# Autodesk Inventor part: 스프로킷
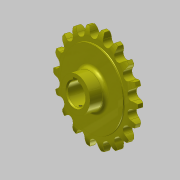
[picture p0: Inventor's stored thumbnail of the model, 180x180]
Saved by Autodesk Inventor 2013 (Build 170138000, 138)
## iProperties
Created: 2016-03
Part Number: 스프로킷
Material: 강철, 탄소
Document SubType Name: Modeling
Designer: mduedu
Density: 7.87 g/cm^3
Mass: 300.005 g
Surface Area: 127.848 cm^2
Volume: 38.12 cm^3
Author: mduedu
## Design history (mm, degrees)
sketch "스케치1"
  geometry: L1 (0, 5)-(29.5, 5); L2 (29.5, 5)-(29.5, 4.1); L3 (30, 3.6)-(33.625, 3.6); L4 (40, 2)-(40, 0); L5 (40, 0)-(0, 0); L6 (0, 0)-(0, 5); L7 (0, -5)-(29.5, -5); L8 (29.5, -5)-(29.5, -4.1); L9 (30, -3.6)-(33.625, -3.6); L10 (40, -2)-(40, 0); L11 (0, 0)-(0, -5); A1 r 13.5 centre (33.625, -9.9) between (40, 2) and (33.625, 3.6); A2 r 13.5 centre (33.625, 9.9) between (33.625, -3.6) and (40, -2); A3 r 0.5 centre (30, 4.1) between (29.5, 4.1) and (30, 3.6); A4 r 0.5 centre (30, -4.1) between (30, -3.6) and (29.5, -4.1); 2 further points
  constraints: 22 end point, 8 point on circle, 6 symmetric about line, 5 tangent, 4 centre point, 4 parallel, 4 point on line, 1 equal radius, 1 horizontal, 1 perpendicular, 1 other
  dimensions: "d0" = 80 diameter of L4 L6; "d2" = 59 diameter of L2 L6; "d3" = 1.6 vertical distance of L4.start L3.end; "d4" = 3.6 distance from line of L4.end L3; "d5" = 5 distance between parallel lines of L5 L1; "d6" = 13.5 radius of A1; "d15" = 0.5 radius of A3
revolve "회전1" sketch "스케치1" stored, may be unused: angle "d7" = 90 deg
sketch "스케치2" dims "d8" = 65.2, "d11" = 80
  geometry: L1 (0, 0)-(0, 32.6); A1 r 36.57 centre (0, 0) between (-16.231, 32.771) and (0, 36.57); A2 r 3.97 centre (0, 36.57) between (-3.866, 35.665) and (0, 32.6); A3 r 12.7 centre (-16.231, 32.771) between (-3.866, 35.665) and (-5.534, 39.615); A4 r 12.7 centre (16.231, 32.771) between (5.534, 39.615) and (3.866, 35.665); A5 r 3.97 centre (0, 36.57) between (0, 32.6) and (3.866, 35.665); A6 r 40 centre (0, 0) between (5.534, 39.615) and (-5.534, 39.615); 2 further points
  constraints: 12 point on circle, 6 centre point, 4 coincident, 3 symmetric about line, 2 end point, 1 point on line, 1 tangent, 1 vertical, 1 vertical alignment, 7 other
  dimensions: "d10" = 73.14 diameter of A1; "d12" = 12.7 radius of A3
extrude "돌출1" cut sketch "스케치2" stored distance "d13" = 10; taper "d14" = 0 deg
sketch "스케치3"
  geometry: C1 r 13.5 at (0, 0); 1 further point
  constraints: 1 centre point, 1 coincident
  dimensions: "d19" = 27 diameter of C1
extrude "돌출2" join sketch "스케치3" distance "d20" = 13; taper "d21" = 0 deg
fillet "모깎기1" dims "d22" = 3
sketch "스케치4"
  geometry: L1 (-2.5, 0)-(2.5, 0); L2 (2.5, 0)-(2.5, 10.8); L3 (2.5, 10.8)-(-2.5, 10.8); L4 (-2.5, 10.8)-(-2.5, 0); C1 r 8.5 at (0, 0); 2 further points
  constraints: 8 end point, 2 coincident, 2 parallel, 1 centre point, 1 horizontal, 1 midpoint, 1 perpendicular
  dimensions: "d23" = 17 diameter of C1; "d25" = 5 distance of L2.end L3.end; "d26" = 10.8 distance of L1.end L2.end
extrude "돌출3" cut sketch "스케치4" stored distance "d27" = 8; taper "d28" = 0 deg
chamfer "모따기1" distance "d29" = 1; stored, may be unused: second distance "d30" = 2, angle "d31" = 45 deg
node "작업 평면1"
sketch "스케치5"
  geometry: L1 (13.5, 13)-(-13.5, 13) reference; 2 further points
  constraints: 1 vertical alignment
  dimensions: "d32" = 4 distance from line of point (0, 9) L1
hole "구멍1" sketch "스케치5" at (0, 9) diameter "d33" = 2.459; stored, may be unused: countersink angle "d37" = 90 deg, drill point angle "d39" = 118 deg; dims "d34" = 6, "d35" = 4, "d36" = 2, "d38" = 8
node "솔리드1"
pattern_circular "원형 패턴1" dims angle "d17" = 360 deg
